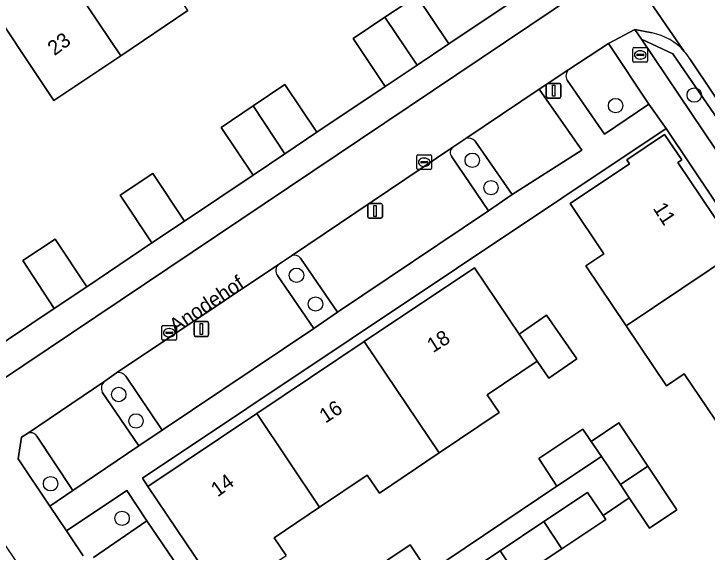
# Model space of a CAD drawing. Extents: x 158793 to 159888, y 384317 to 385256.
# Drawn here: x 158909.67 to 158956.72, y 384509.06 to 384545.6 of the extents above; entities that cross this region are included whole.
import ezdxf

# ---------------------------------------------------------------- set-up
doc = ezdxf.new("R2010")
doc.units = 0
for name, color, linetype in [('IMGEO_Boom', 7, 'Continuous'), ('IMGEO_Brandkraan', 7, 'Continuous'), ('IMGEO_Erf', 7, 'Continuous'), ('IMGEO_Groenvoorziening', 7, 'Continuous'), ('IMGEO_Haag', 7, 'Continuous'), ('IMGEO_Kolk', 7, 'Continuous'), ('IMGEO_Lichtmast', 7, 'Continuous'), ('IMGEO_Openbare_ruimte_label', 7, 'Continuous'), ('IMGEO_Pand', 7, 'Continuous'), ('IMGEO_Pand_nummerreeks', 7, 'Continuous'), ('IMGEO_Parkeervlak_open', 7, 'Continuous'), ('IMGEO_Rijbaan_lokaal_open', 7, 'Continuous'), ('IMGEO_Voetpad_open', 7, 'Continuous')]:
    doc.layers.add(name, color=color, linetype=linetype)

msp = doc.modelspace()

# ---------------------------------------------------------------- linework, layer by layer
at = {"layer": 'IMGEO_Boom'}
for centre in [(158955.848, 384540.084), (158950.512, 384539.367), (158940.785, 384535.657), (158942.054, 384533.799), (158928.854, 384527.853), (158930.146, 384525.901), (158916.791, 384519.759), (158917.965, 384517.966), (158912.17, 384513.703), (158917.017, 384511.355)]:
    msp.add_circle(centre, 0.489, dxfattribs=at)
at = {"layer": 'IMGEO_Brandkraan'}
for p, q in [((158951.758, 384543.308), (158952.61, 384543.308)), ((158951.683, 384542.382), (158951.683, 384543.234)), ((158951.985, 384542.851), (158952.383, 384542.851)), ((158952.171, 384543.088), (158952.196, 384543.088)), ((158952.684, 384543.234), (158952.684, 384542.382)), ((158951.942, 384542.802), (158951.942, 384542.814)), ((158952.38, 384542.765), (158951.982, 384542.765)), ((158952.194, 384542.528), (158952.169, 384542.528)), ((158952.426, 384542.814), (158952.426, 384542.802)), ((158952.61, 384542.308), (158951.758, 384542.308))]:
    msp.add_line(p, q, dxfattribs=at)
for points in [[(158951.758, 384543.308), (158952.61, 384543.308)], [(158951.683, 384542.382), (158951.683, 384543.234)], [(158952.684, 384543.234), (158952.684, 384542.382)], [(158952.61, 384542.308), (158951.758, 384542.308)]]:
    msp.add_lwpolyline(points, dxfattribs=at)
for centre, radius, start, end in [((158951.76, 384543.232), 0.0765, 91.552, 178.448), ((158951.76, 384543.232), 0.0765, 91.552, 178.448), ((158952.608, 384543.232), 0.0765, 1.552, 88.448), ((158952.608, 384543.232), 0.0765, 1.552, 88.448), ((158951.982, 384542.811), 0.0403, 85.8775, 175.7526), ((158952.387, 384542.813), 0.0386, 1.7309, 96.639), ((158951.76, 384542.384), 0.0765, 181.552, 268.448), ((158951.76, 384542.384), 0.0765, 181.552, 268.448), ((158951.979, 384542.801), 0.0366, 178.938, 274.7102), ((158952.383, 384542.808), 0.043, 264.8664, 352.4533), ((158952.608, 384542.384), 0.0765, 271.552, 358.448), ((158952.608, 384542.384), 0.0765, 271.552, 358.448)]:
    msp.add_arc(centre, radius, start, end, dxfattribs=at)
for centre, major_axis, ratio, start_param, end_param in [((158952.17, 384542.808), (-0.387, 0.002), 0.722429, 4.712389, 7.853982), ((158952.195, 384542.808), (-0.39, 0.002), 0.717154, 1.570796, 4.712389)]:
    msp.add_ellipse(centre, major_axis=major_axis, ratio=ratio, start_param=start_param, end_param=end_param, dxfattribs=at)
at = {"layer": 'IMGEO_Erf'}
for points in [[(158921.471, 384545.817), (158916.94, 384542.749), (158912.383, 384539.719), (158907.238, 384547.447)], [(158907.773, 384522.506), (158912.413, 384525.602), (158910.273, 384528.849), (158912.485, 384530.307), (158914.625, 384527.06), (158919.042, 384530.05), (158916.884, 384533.29), (158919.099, 384534.766), (158921.257, 384531.526), (158925.904, 384534.654), (158923.733, 384537.891), (158925.904, 384539.347), (158928.074, 384540.803), (158930.245, 384537.566), (158934.873, 384540.668), (158932.692, 384543.924), (158934.86, 384545.376), (158937.015, 384546.82), (158939.196, 384543.564), (158943.959, 384546.786)], [(158975.088, 384506.233), (158953.94, 384537.814), (158918.394, 384514.076), (158918.769, 384513.517), (158926.159, 384518.467), (158933.458, 384523.355), (158940.939, 384528.366), (158943.961, 384523.865), (158945.816, 384525.151), (158947.88, 384522.174), (158945.98, 384520.857), (158945.197, 384522.024), (158941.801, 384519.738), (158942.612, 384518.534), (158938.545, 384515.803), (158934.479, 384513.072), (158933.66, 384514.293), (158930.419, 384512.107), (158927.349, 384510.037), (158928.161, 384508.831)], [(158964.755, 384504.258), (158961.47, 384509.156), (158958.173, 384514.044), (158959.392, 384514.865), (158957.28, 384518.014), (158955.155, 384521.156), (158953.954, 384520.354), (158951.224, 384524.423), (158948.495, 384528.492), (158949.716, 384529.311), (158947.419, 384532.718), (158951.464, 384535.411), (158951.273, 384535.691), (158953.82, 384537.41), (158955.001, 384535.679), (158954.74, 384535.502), (158958.776, 384529.488), (158963.621, 384522.268), (158969.022, 384514.221), (158974.565, 384505.899)], [(158933.602, 384507.575), (158936.57, 384509.546), (158937.81, 384507.679), (158946.52, 384513.53), (158945.292, 384515.412), (158948.296, 384517.404), (158948.843, 384516.579), (158950.738, 384517.836), (158952.707, 384514.889), (158954.676, 384511.942), (158952.805, 384510.692), (158951.441, 384512.734), (158949.656, 384511.544), (158949.841, 384511.267), (158946.867, 384509.284), (158943.9, 384507.305), (158942.671, 384509.148), (158939.625, 384507.135)]]:
    msp.add_lwpolyline(points, dxfattribs=at)
at = {"layer": 'IMGEO_Groenvoorziening'}
for points in [[(158952.985, 384544.3), (158951.825, 384544.524), (158952.256, 384543.886), (158954.383, 384542.884), (158960.048, 384534.651), (158960.593, 384535.015), (158955.547, 384542.547)], [(158947.228, 384541.089), (158949.748, 384537.433), (158952.774, 384539.473), (158950.024, 384543.596), (158947.346, 384541.827)], [(158939.397, 384535.884), (158941.89, 384532.222), (158943.481, 384533.325), (158940.99, 384536.947)], [(158940.342, 384537.141), (158939.465, 384536.543)], [(158927.555, 384527.835), (158930.042, 384524.233), (158931.63, 384525.348), (158929.135, 384529.016)], [(158928.525, 384529.173), (158927.633, 384528.594)], [(158916.651, 384521.222), (158915.837, 384520.657)], [(158915.671, 384519.921), (158918.154, 384516.285), (158919.737, 384517.344), (158917.263, 384521.009)], [(158910.602, 384517.109), (158910.194, 384516.853), (158909.958, 384515.383), (158912.116, 384512.177), (158913.683, 384513.236), (158911.225, 384516.94)], [(158915.08, 384508.692), (158918.697, 384511.189), (158917.334, 384513.24), (158913.236, 384510.512), (158914.389, 384508.81)]]:
    msp.add_lwpolyline(points, dxfattribs=at)
msp.add_lwpolyline([(158952.256, 384543.886), (158958.971, 384533.932), (158960.048, 384534.651), (158954.383, 384542.884)], close=True, dxfattribs=at)
for centre, radius, start, end in [((158952.239, 384540.461), 3.911, 41.3964, 79.0068), ((158952.316, 384540.52), 3.814, 32.1011, 41.4919), ((158947.7, 384541.392), 0.561, 129.1136, 212.7179), ((158940.505, 384536.506), 0.656, 42.28, 104.3864), ((158939.724, 384536.183), 0.443, 125.726, 222.4914), ((158928.728, 384528.697), 0.517, 38.0485, 113.0848), ((158928.018, 384528.171), 0.572, 132.3213, 215.9437), ((158916.809, 384520.689), 0.556, 35.1535, 106.4667), ((158916.219, 384520.184), 0.608, 128.9242, 205.6558), ((158910.827, 384516.704), 0.463, 30.6039, 119.0416)]:
    msp.add_arc(centre, radius, start, end, dxfattribs=at)
at = {"layer": 'IMGEO_Haag'}
msp.add_lwpolyline([(158952.985, 384544.3), (158951.825, 384544.524), (158952.256, 384543.886), (158954.383, 384542.884), (158960.048, 384534.651), (158960.593, 384535.015), (158955.547, 384542.547)], dxfattribs=at)
for centre, radius, start, end in [((158952.239, 384540.461), 3.911, 41.3964, 79.0068), ((158952.316, 384540.52), 3.814, 32.1011, 41.4919)]:
    msp.add_arc(centre, radius, start, end, dxfattribs=at)
at = {"layer": 'IMGEO_Kolk'}
for p, q in [((158937.024, 384535.099), (158937.024, 384535.951)), ((158937.099, 384536.025), (158937.951, 384536.025)), ((158937.512, 384535.805), (158937.537, 384535.805)), ((158938.025, 384535.951), (158938.025, 384535.099)), ((158937.283, 384535.519), (158937.283, 384535.531)), ((158937.721, 384535.482), (158937.323, 384535.482)), ((158937.326, 384535.568), (158937.724, 384535.568)), ((158937.767, 384535.531), (158937.767, 384535.519)), ((158937.951, 384535.025), (158937.099, 384535.025)), ((158937.535, 384535.245), (158937.51, 384535.245)), ((158919.719, 384523.524), (158919.719, 384524.376)), ((158919.794, 384524.45), (158920.646, 384524.45)), ((158920.207, 384524.23), (158920.232, 384524.23)), ((158920.72, 384524.376), (158920.72, 384523.524)), ((158919.978, 384523.944), (158919.978, 384523.956)), ((158920.416, 384523.907), (158920.018, 384523.907)), ((158920.021, 384523.993), (158920.419, 384523.993)), ((158920.23, 384523.67), (158920.205, 384523.67)), ((158920.462, 384523.956), (158920.462, 384523.944)), ((158920.646, 384523.45), (158919.794, 384523.45))]:
    msp.add_line(p, q, dxfattribs=at)
for points in [[(158937.024, 384535.099), (158937.024, 384535.951)], [(158937.099, 384536.025), (158937.951, 384536.025)], [(158938.025, 384535.951), (158938.025, 384535.099)], [(158937.951, 384535.025), (158937.099, 384535.025)], [(158919.719, 384523.524), (158919.719, 384524.376)], [(158919.794, 384524.45), (158920.646, 384524.45)], [(158920.72, 384524.376), (158920.72, 384523.524)], [(158920.646, 384523.45), (158919.794, 384523.45)]]:
    msp.add_lwpolyline(points, dxfattribs=at)
for centre, radius, start, end in [((158937.101, 384535.949), 0.0765, 91.552, 178.448), ((158937.101, 384535.949), 0.0765, 91.552, 178.448), ((158937.949, 384535.949), 0.0765, 1.552, 88.448), ((158937.949, 384535.949), 0.0765, 1.552, 88.448), ((158937.323, 384535.528), 0.0403, 85.8775, 175.7526), ((158937.32, 384535.518), 0.0366, 178.938, 274.7102), ((158937.724, 384535.525), 0.043, 264.8664, 352.4533), ((158937.728, 384535.53), 0.0386, 1.7309, 96.639), ((158937.101, 384535.101), 0.0765, 181.552, 268.448), ((158937.101, 384535.101), 0.0765, 181.552, 268.448), ((158937.949, 384535.101), 0.0765, 271.552, 358.448), ((158937.949, 384535.101), 0.0765, 271.552, 358.448), ((158919.796, 384524.374), 0.0765, 91.552, 178.448), ((158919.796, 384524.374), 0.0765, 91.552, 178.448), ((158920.644, 384524.374), 0.0765, 1.552, 88.448), ((158920.644, 384524.374), 0.0765, 1.552, 88.448), ((158920.018, 384523.953), 0.0403, 85.8775, 175.7526), ((158920.015, 384523.943), 0.0366, 178.938, 274.7102), ((158920.419, 384523.95), 0.043, 264.8664, 352.4533), ((158920.423, 384523.955), 0.0386, 1.7309, 96.639), ((158919.796, 384523.526), 0.0765, 181.552, 268.448), ((158919.796, 384523.526), 0.0765, 181.552, 268.448), ((158920.644, 384523.526), 0.0765, 271.552, 358.448), ((158920.644, 384523.526), 0.0765, 271.552, 358.448)]:
    msp.add_arc(centre, radius, start, end, dxfattribs=at)
for centre, major_axis, ratio, start_param, end_param in [((158937.511, 384535.525), (-0.387, 0.002), 0.722429, 4.712389, 7.853982), ((158937.536, 384535.525), (-0.39, 0.002), 0.717154, 1.570796, 4.712389), ((158920.206, 384523.95), (-0.387, 0.002), 0.722429, 4.712389, 7.853982), ((158920.231, 384523.95), (-0.39, 0.002), 0.717154, 1.570796, 4.712389)]:
    msp.add_ellipse(centre, major_axis=major_axis, ratio=ratio, start_param=start_param, end_param=end_param, dxfattribs=at)
at = {"layer": 'IMGEO_Lichtmast'}
for p, q in [((158945.808, 384539.979), (158945.808, 384540.779)), ((158945.808, 384540.779), (158945.808, 384539.979)), ((158945.908, 384540.879), (158946.698, 384540.879)), ((158946.698, 384540.879), (158945.908, 384540.879)), ((158946.798, 384540.779), (158946.798, 384539.979)), ((158946.798, 384539.979), (158946.798, 384540.779)), ((158946.698, 384539.879), (158945.908, 384539.879)), ((158945.908, 384539.879), (158946.698, 384539.879)), ((158933.69, 384531.821), (158933.69, 384532.621)), ((158933.69, 384532.621), (158933.69, 384531.821)), ((158933.79, 384532.721), (158934.58, 384532.721)), ((158934.58, 384532.721), (158933.79, 384532.721)), ((158934.68, 384532.621), (158934.68, 384531.821)), ((158934.68, 384531.821), (158934.68, 384532.621)), ((158934.58, 384531.721), (158933.79, 384531.721)), ((158933.79, 384531.721), (158934.58, 384531.721)), ((158921.902, 384523.804), (158921.902, 384524.604)), ((158921.902, 384524.604), (158921.902, 384523.804)), ((158922.002, 384524.704), (158922.792, 384524.704)), ((158922.792, 384524.704), (158922.002, 384524.704)), ((158922.892, 384524.604), (158922.892, 384523.804)), ((158922.892, 384523.804), (158922.892, 384524.604)), ((158922.792, 384523.704), (158922.002, 384523.704)), ((158922.002, 384523.704), (158922.792, 384523.704))]:
    msp.add_line(p, q, dxfattribs=at)
for points in [[(158946.228, 384540.754), (158946.378, 384540.754), (158946.378, 384540.004), (158946.228, 384540.004), (158946.228, 384540.754)], [(158934.11, 384532.596), (158934.26, 384532.596), (158934.26, 384531.846), (158934.11, 384531.846), (158934.11, 384532.596)], [(158922.322, 384524.579), (158922.472, 384524.579), (158922.472, 384523.829), (158922.322, 384523.829), (158922.322, 384524.579)]]:
    msp.add_lwpolyline(points, dxfattribs=at)
for centre, start, end in [((158945.908, 384540.779), 90, 180), ((158945.908, 384540.779), 90, 180), ((158946.698, 384540.779), 0, 90), ((158946.698, 384540.779), 360, 90), ((158945.908, 384539.979), 180, 270), ((158945.908, 384539.979), 180, 270), ((158946.698, 384539.979), 270, 0), ((158946.698, 384539.979), 270, 0), ((158933.79, 384532.621), 90, 180), ((158933.79, 384532.621), 90, 180), ((158934.58, 384532.621), 0, 90), ((158934.58, 384532.621), 360, 90), ((158933.79, 384531.821), 180, 270), ((158933.79, 384531.821), 180, 270), ((158934.58, 384531.821), 270, 0), ((158934.58, 384531.821), 270, 0), ((158922.002, 384524.604), 90, 180), ((158922.002, 384524.604), 90, 180), ((158922.792, 384524.604), 0, 90), ((158922.792, 384524.604), 360, 90), ((158922.002, 384523.804), 180, 270), ((158922.002, 384523.804), 180, 270), ((158922.792, 384523.804), 270, 0), ((158922.792, 384523.804), 270, 0)]:
    msp.add_arc(centre, 0.1, start, end, dxfattribs=at)
at = {"layer": 'IMGEO_Pand'}
for points in [[(158911.747, 384550.473), (158916.94, 384542.749), (158921.471, 384545.817), (158916.291, 384553.522)], [(158911.747, 384550.473), (158907.238, 384547.447), (158912.383, 384539.719), (158916.94, 384542.749)], [(158934.86, 384545.376), (158937.034, 384542.116), (158939.196, 384543.564), (158937.015, 384546.82)], [(158934.86, 384545.376), (158932.692, 384543.924), (158934.873, 384540.668), (158937.034, 384542.116)], [(158928.066, 384536.105), (158930.245, 384537.566), (158928.074, 384540.803), (158925.904, 384539.347)], [(158928.066, 384536.105), (158925.904, 384539.347), (158923.733, 384537.891), (158925.904, 384534.654)], [(158951.224, 384524.423), (158958.776, 384529.488), (158954.74, 384535.502), (158955.001, 384535.679), (158953.82, 384537.41), (158951.273, 384535.691), (158951.464, 384535.411), (158947.419, 384532.718), (158949.716, 384529.311), (158948.495, 384528.492)], [(158921.257, 384531.526), (158919.099, 384534.766), (158916.884, 384533.29), (158919.042, 384530.05)], [(158912.413, 384525.602), (158914.625, 384527.06), (158912.485, 384530.307), (158910.273, 384528.849)], [(158951.224, 384524.423), (158953.954, 384520.354), (158955.155, 384521.156), (158957.28, 384518.014), (158963.621, 384522.268), (158958.776, 384529.488)], [(158943.961, 384523.865), (158940.939, 384528.366), (158933.458, 384523.355), (158938.545, 384515.803), (158942.612, 384518.534), (158941.801, 384519.738), (158945.197, 384522.024)], [(158943.961, 384523.865), (158945.197, 384522.024), (158945.98, 384520.857), (158947.88, 384522.174), (158945.816, 384525.151)], [(158926.159, 384518.467), (158930.419, 384512.107), (158933.66, 384514.293), (158934.479, 384513.072), (158938.545, 384515.803), (158933.458, 384523.355)], [(158926.159, 384518.467), (158918.769, 384513.517), (158923.869, 384505.933), (158928.161, 384508.831), (158927.349, 384510.037), (158930.419, 384512.107)], [(158952.707, 384514.889), (158950.738, 384517.836), (158948.843, 384516.579), (158949.556, 384515.555), (158950.836, 384513.639)], [(158948.843, 384516.579), (158948.296, 384517.404), (158945.292, 384515.412), (158946.52, 384513.53), (158949.556, 384515.555)], [(158952.707, 384514.889), (158950.836, 384513.639), (158951.441, 384512.734), (158952.805, 384510.692), (158954.676, 384511.942)], [(158949.841, 384511.267), (158949.656, 384511.544), (158948.612, 384513.11), (158945.642, 384511.129), (158946.867, 384509.284)], [(158946.867, 384509.284), (158945.642, 384511.129), (158942.671, 384509.148), (158943.9, 384507.305)], [(158933.602, 384507.575), (158934.842, 384505.708), (158937.81, 384507.679), (158936.57, 384509.546)]]:
    msp.add_lwpolyline(points, close=True, dxfattribs=at)
at = {"layer": 'IMGEO_Parkeervlak_open'}
for points in [[(158940.99, 384536.947), (158943.481, 384533.325), (158948.224, 384536.354), (158945.328, 384540.494), (158940.342, 384537.141)], [(158939.465, 384536.543), (158928.525, 384529.173)], [(158929.135, 384529.016), (158931.63, 384525.348), (158941.89, 384532.222), (158939.397, 384535.884)], [(158927.633, 384528.594), (158916.651, 384521.222)], [(158917.263, 384521.009), (158919.737, 384517.344), (158930.042, 384524.233), (158927.555, 384527.835)], [(158915.837, 384520.657), (158910.602, 384517.109)], [(158911.225, 384516.94), (158913.683, 384513.236), (158918.154, 384516.285), (158915.671, 384519.921)], [(158918.244, 384503.977), (158921.89, 384506.498), (158918.697, 384511.189), (158915.08, 384508.692)]]:
    msp.add_lwpolyline(points, dxfattribs=at)
for centre, radius, start, end in [((158940.505, 384536.506), 0.656, 42.28, 104.3864), ((158939.724, 384536.183), 0.443, 125.726, 222.4914), ((158928.728, 384528.697), 0.517, 38.0485, 113.0848), ((158928.018, 384528.171), 0.572, 132.3213, 215.9437), ((158916.809, 384520.689), 0.556, 35.1535, 106.4667), ((158916.219, 384520.184), 0.608, 128.9242, 205.6558), ((158910.827, 384516.704), 0.463, 30.6039, 119.0416)]:
    msp.add_arc(centre, radius, start, end, dxfattribs=at)
at = {"layer": 'IMGEO_Rijbaan_lokaal_open'}
for points in [[(158957.261, 384548.86), (158939.124, 384575.906), (158934.884, 384573.077), (158938.217, 384568.343), (158938.247, 384568.298), (158938.8, 384567.475), (158948.753, 384552.386), (158955.173, 384543.047)], [(158955.173, 384543.047), (158948.753, 384552.386)], [(158949.297, 384549.549), (158949.066, 384548.587), (158947.914, 384546.992), (158903.79, 384517.357), (158937.214, 384467.664), (158981.152, 384497.194)], [(158914.389, 384508.81), (158913.236, 384510.512), (158912.116, 384512.177), (158909.958, 384515.383), (158910.194, 384516.853), (158910.602, 384517.109), (158915.837, 384520.657), (158916.651, 384521.222), (158927.633, 384528.594), (158928.525, 384529.173), (158939.465, 384536.543), (158940.342, 384537.141), (158945.328, 384540.494), (158947.346, 384541.827), (158950.024, 384543.596), (158951.825, 384544.524), (158952.985, 384544.3)], [(158955.547, 384542.547), (158960.593, 384535.015), (158961.728, 384533.384), (158979.132, 384507.356)]]:
    msp.add_lwpolyline(points, dxfattribs=at)
for centre, radius, start, end in [((158952.239, 384540.461), 3.911, 41.3964, 79.0068), ((158952.316, 384540.52), 3.814, 32.1011, 41.4919)]:
    msp.add_arc(centre, radius, start, end, dxfattribs=at)
at = {"layer": 'IMGEO_Voetpad_open'}
for points in [[(158903.79, 384517.357), (158947.914, 384546.992), (158946.771, 384548.676), (158946.146, 384548.258), (158943.959, 384546.786), (158939.196, 384543.564), (158937.034, 384542.116), (158934.873, 384540.668), (158930.245, 384537.566), (158928.066, 384536.105), (158925.904, 384534.654), (158921.257, 384531.526), (158919.042, 384530.05), (158914.625, 384527.06), (158912.413, 384525.602), (158907.773, 384522.506)], [(158960.098, 384532.253), (158961.142, 384532.977), (158961.728, 384533.384), (158960.593, 384535.015), (158960.048, 384534.651), (158958.971, 384533.932), (158952.256, 384543.886), (158951.825, 384544.524), (158950.024, 384543.596), (158952.774, 384539.473), (158953.94, 384537.814), (158975.088, 384506.233), (158976.234, 384504.561), (158978.721, 384500.843)], [(158947.346, 384541.827), (158945.328, 384540.494), (158948.224, 384536.354), (158943.481, 384533.325), (158941.89, 384532.222), (158931.63, 384525.348), (158930.042, 384524.233), (158919.737, 384517.344), (158918.154, 384516.285), (158913.683, 384513.236), (158912.116, 384512.177), (158913.236, 384510.512), (158917.334, 384513.24), (158918.697, 384511.189), (158921.89, 384506.498), (158922.938, 384504.944), (158925.986, 384500.523), (158927.06, 384501.18), (158923.869, 384505.933), (158918.769, 384513.517), (158918.394, 384514.076), (158953.94, 384537.814)], [(158953.94, 384537.814), (158952.774, 384539.473), (158949.748, 384537.433), (158947.228, 384541.089)]]:
    msp.add_lwpolyline(points, dxfattribs=at)
msp.add_lwpolyline([(158939.625, 384507.135), (158942.671, 384509.148), (158945.642, 384511.129), (158948.612, 384513.11), (158949.656, 384511.544), (158951.441, 384512.734), (158950.836, 384513.639), (158949.556, 384515.555), (158946.52, 384513.53), (158937.81, 384507.679), (158934.842, 384505.708), (158931.873, 384503.736), (158927.392, 384500.76), (158927.479, 384500.65), (158922.273, 384497.113), (158923.029, 384495.988), (158924.741, 384497.137), (158927.71, 384499.119), (158929.183, 384500.102), (158932.135, 384502.072), (158933.708, 384503.138), (158936.667, 384505.136)], close=True, dxfattribs=at)
msp.add_arc((158947.7, 384541.392), 0.561, 129.1136, 212.7179, dxfattribs=at)

# ---------------------------------------------------------------- texts
at = {"layer": 'IMGEO_Openbare_ruimte_label'}
msp.add_text('Anodehof', height=1, rotation=33.7854, dxfattribs=at).set_placement((158920.642, 384523.876))
at = {"layer": 'IMGEO_Pand_nummerreeks'}
for s, rotation, p in [('23', 36.4396, (158912.431, 384542.721)), ('11', 303.1701, (158953.012, 384532.394)), ('18', 32.2248, (158938.115, 384522.559)), ('16', 33.3347, (158930.827, 384517.779)), ('14', 35.6988, (158923.504, 384512.768))]:
    msp.add_text(s, height=1, rotation=rotation, dxfattribs=at).set_placement(p)

doc.saveas('drawing.dxf')
